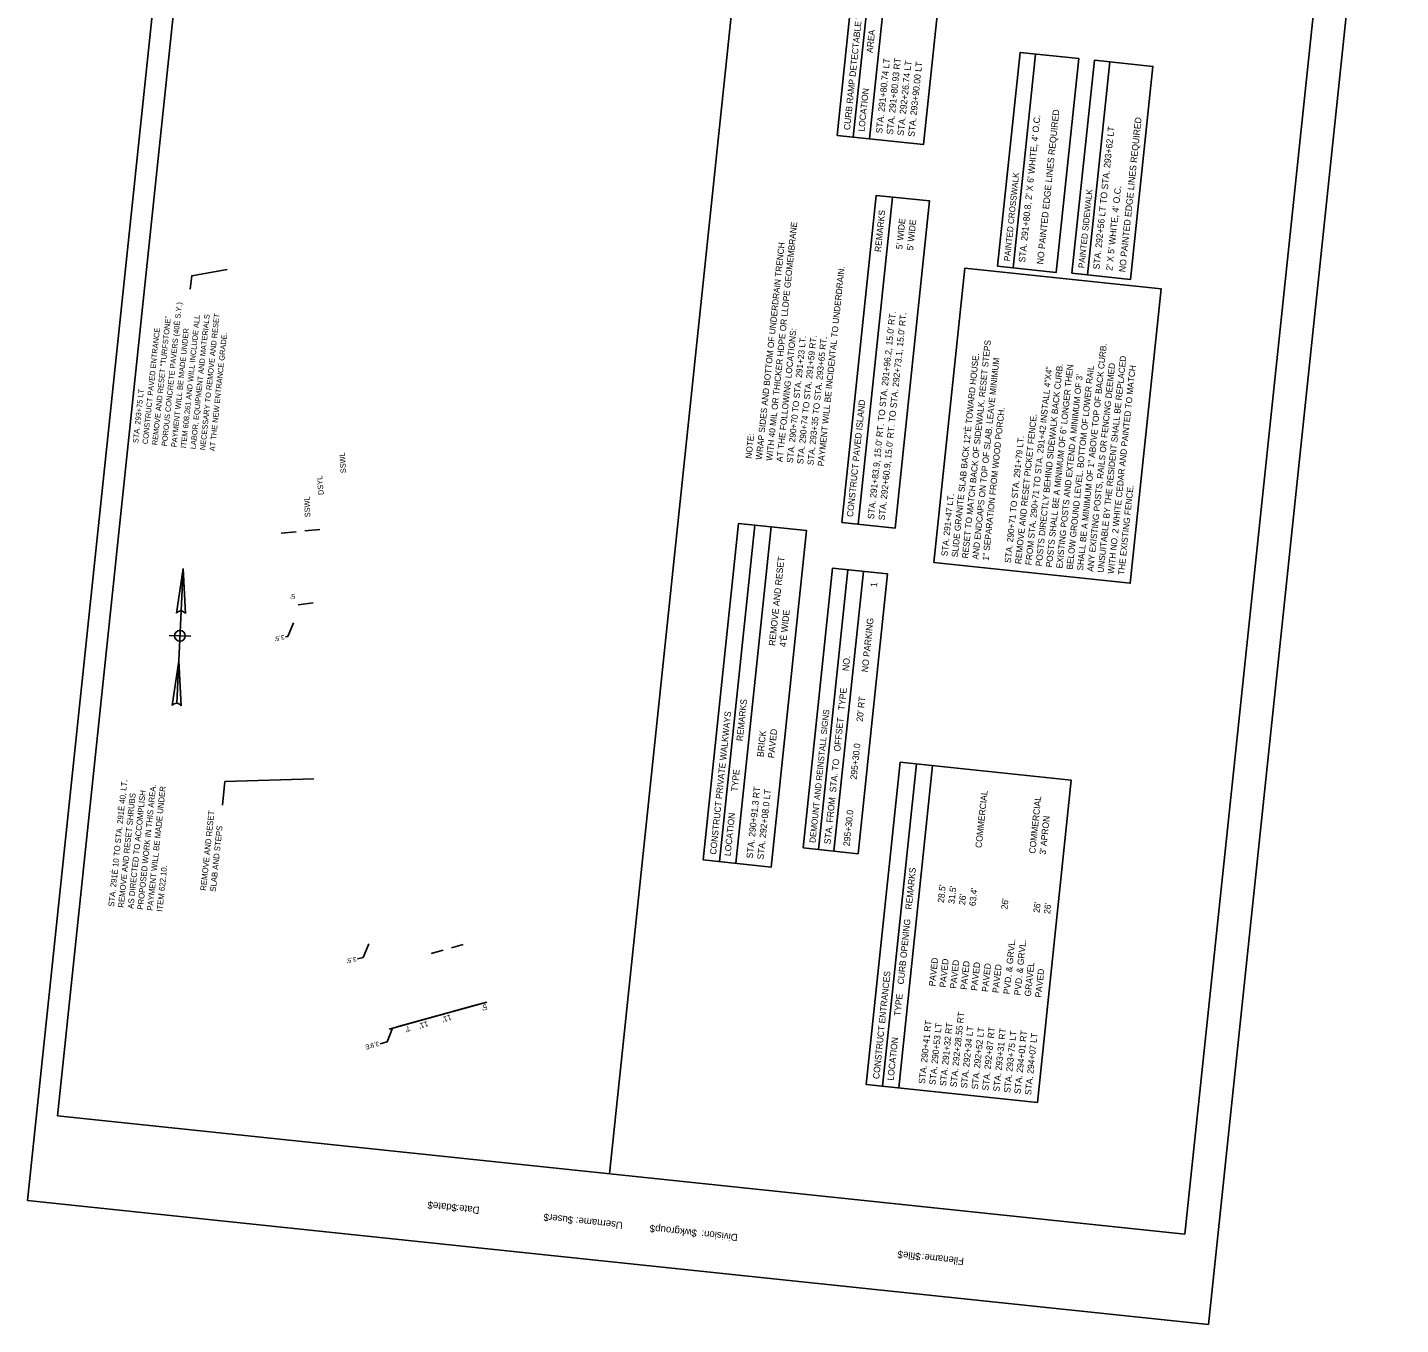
# Model space of a CAD drawing. Extents: x 1111051 to 1111686, y 618367 to 619270.
# Drawn here: x 1111051 to 1111686, y 618367 to 618968 of the extents above; entities that cross this region are included whole.
import ezdxf

# ---------------------------------------------------------------- set-up
doc = ezdxf.new("R2010")
doc.units = 0
for name, color, linetype in [('D_Roadway_Centerline_Text', 7, 'Continuous'), ('MINOR', 7, 'Continuous'), ('S_Roadway_Sidewalks_Paved', 7, 'Continuous'), ('S_Utilities_GuyWire3', 7, 'Continuous')]:
    doc.layers.add(name, color=color, linetype=linetype)

msp = doc.modelspace()

# ---------------------------------------------------------------- linework, layer by layer
at = {"layer": 'D_Roadway_Centerline_Text'}
for p, q in [((1111119.63, 618696.79), (1111122.67, 618717.51)), ((1111122.67, 618717.51), (1111119.81, 618655.07)), ((1111122.67, 618717.51), (1111123.79, 618696.6)), ((1111116.24, 618686.52), (1111126.23, 618686.06)), ((1111117.68, 618654.05), (1111120.71, 618674.77)), ((1111120.71, 618674.77), (1111121.84, 618653.86))]:
    msp.add_line(p, q, dxfattribs=at)
msp.add_circle((1111121.24, 618686.29), 2.5, dxfattribs=at)
for centre in [(1111121.65, 618695.31), (1111119.69, 618652.57)]:
    msp.add_arc(centre, 2.5, 30.93571, 143.82109, dxfattribs=at)
at = {"layer": 'MINOR'}
for p, q in [((1111148.14, 619259.69), (1111064.52, 618464.07)), ((1111586.64, 618409.2), (1111670.26, 619204.81)), ((1111320.11, 618437.21), (1111398.5, 619183.1)), ((1111064.52, 618464.07), (1111586.64, 618409.2))]:
    msp.add_line(p, q, dxfattribs=at)
at = {"layer": 'S_Roadway_Sidewalks_Paved'}
msp.add_lwpolyline([(1111597.62, 618367.35), (1111686.47, 619212.69), (1111139.49, 619270.18), (1111050.64, 618424.84)], close=True, dxfattribs=at)
at = {"layer": 'S_Utilities_GuyWire3'}
for p, q in [((1111433.07, 618917.25), (1111444.25, 619023.7)), ((1111440.6, 618916.46), (1111451.79, 619022.91)), ((1111507.04, 618856.69), (1111517.45, 618955.71)), ((1111541.48, 618853.48), (1111551.85, 618952.09)), ((1111435.31, 618738), (1111451.23, 618889.46)), ((1111371.08, 618581.73), (1111387.46, 618737.58)), ((1111168.1, 618733.85), (1111175.07, 618734.51)), ((1111186.02, 618735.56), (1111179.05, 618734.89)), ((1111378.61, 618580.94), (1111394.99, 618736.79)), ((1111416.95, 618587.31), (1111430.57, 618716.87)), ((1111424.11, 618586.56), (1111437.72, 618716.12)), ((1111176.03, 618700.65), (1111182.96, 618701.63)), ((1111182.96, 618701.63), (1111176.03, 618700.65)), ((1111446.57, 618477.79), (1111462.25, 618626.97)), ((1111454.1, 618477), (1111469.78, 618626.18)), ((1111237.53, 618539.14), (1111243.14, 618540.7)), ((1111252.43, 618543.27), (1111246.99, 618541.76)), ((1111247.94, 618512.42), (1111258.54, 618515.36)), ((1111261.43, 618516.16), (1111250.83, 618513.23)), ((1111240.23, 618510.29), (1111229.62, 618507.36)), ((1111229.63, 618507.36), (1111240.23, 618510.29)), ((1111240.23, 618510.29), (1111250.83, 618513.23)), ((1111250.83, 618513.23), (1111240.23, 618510.29)), ((1111221.69, 618505.16), (1111229.62, 618507.36)), ((1111233.5, 618508.43), (1111222.9, 618505.49))]:
    msp.add_line(p, q, dxfattribs=at)
for points in [[(1111425.53, 618918.04), (1111436.72, 619024.49), (1111476.79, 619020.28), (1111465.6, 618913.83)], [(1111499.88, 618857.45), (1111510.29, 618956.46), (1111537.44, 618953.6), (1111527.03, 618854.59)], [(1111534.32, 618854.23), (1111544.69, 618952.84), (1111571.84, 618949.99), (1111561.47, 618851.37)], [(1111427.78, 618738.79), (1111443.7, 618890.25), (1111468.37, 618887.66), (1111452.45, 618736.2)], [(1111470.37, 618720.19), (1111484.7, 618856.49), (1111575.63, 618846.94), (1111561.31, 618710.63)], [(1111363.54, 618582.52), (1111379.92, 618738.37), (1111411.42, 618735.06), (1111395.04, 618579.21)], [(1111409.79, 618588.06), (1111423.41, 618717.62), (1111448.91, 618714.94), (1111435.29, 618585.38)], [(1111439.03, 618478.58), (1111454.71, 618627.77), (1111533.97, 618619.44), (1111518.29, 618470.25)]]:
    msp.add_lwpolyline(points, close=True, dxfattribs=at)
for points in [[(1111126.02, 618846.76), (1111126.68, 618853.05), (1111143.13, 618855.91)], [(1111170.12, 618685.75), (1111171.14, 618686), (1111173.86, 618692.24)], [(1111140.92, 618607.87), (1111142.07, 618618.81), (1111183.32, 618620.1)], [(1111203.43, 618536.69), (1111206.03, 618537.35), (1111208.76, 618543.59)], [(1111218.06, 618504.15), (1111263.35, 618516.69)], [(1111213.9, 618497.31), (1111217.18, 618498.27), (1111219.68, 618504.6)]]:
    msp.add_lwpolyline(points, dxfattribs=at)

# ---------------------------------------------------------------- texts
at = {"layer": 'MINOR'}
for s, p in [('$date$', (1111249.7, 618422.92)), ('Date:', (1111260.09, 618421.82)), ('$user$', (1111303.48, 618417.26)), ('Username:', (1111326.47, 618414.85)), ('$wkgroup$', (1111360.77, 618411.24)), ('Division:', (1111379.68, 618409.25)), ('$file$', (1111464.42, 618400.35)), ('Filename:', (1111484.44, 618398.24))]:
    msp.add_text(s, height=3.348, rotation=174, dxfattribs=at).set_placement(p)
at = {"layer": 'S_Utilities_GuyWire3'}
for s, height, rotation, p in [('CURB RAMP DETECTABLE WARNING FIELD', 2.9531, 84, (1111431.53, 618920.38)), ('LOCATION               AREA', 2.9531, 84, (1111438.22, 618919.67)), ('STA. 291+80.74 LT', 3.0059, 84, (1111446.43, 618918.81)), ('STA. 291+80.93 RT', 3.0059, 84, (1111451.41, 618918.29)), ('STA. 292+26.74 LT', 3.0059, 84, (1111456.39, 618917.76)), ('STA. 293+90.00 LT', 3.0059, 84, (1111461.37, 618917.24)), ('NO PAINTED EDGE LINES REQUIRED', 3.0059, 83.99894, (1111520.98, 618858.17)), ("STA. 291+80.8, 2' X 6' WHITE, 4' O.C.", 3.0059, 83.99894, (1111512.58, 618859.06)), ('STA. 292+56 LT TO STA. 293+62 LT', 3.0059, 83.99894, (1111547.03, 618855.84)), ('NO PAINTED EDGE LINES REQUIRED', 3.0059, 83.99894, (1111559.02, 618854.58)), ('PAINTED CROSSWALK', 2.8055, 83.99894, (1111505.58, 618859.66)), ('PAINTED SIDEWALK', 2.8055, 83.99894, (1111540.02, 618856.45)), ("2' X 5' WHITE, 4' O.C.", 3.0059, 83.99894, (1111553.02, 618855.21)), ('WITH 40 MIL OR THICKER HDPE OR LLDPE GEOMEMBRANE', 2.88, 84, (1111395.51, 618767.2)), ('REMARKS', 2.953, 84, (1111445.83, 618863.9)), ("5' WIDE", 2.953, 84, (1111455.74, 618865.16)), ("5' WIDE", 2.953, 84, (1111460.72, 618864.64)), ('WRAP SIDES AND BOTTOM OF UNDERDRAIN TRENCH', 2.88, 84, (1111390.74, 618767.71)), ('PAYMENT WILL BE INCIDENTAL TO UNDERDRAIN.', 2.88, 84, (1111419.38, 618764.7)), ('POROUS CONCRETE PAVERS (40È S.Y.)', 2.497, 84, (1111115.21, 618774.01)), ('ITEM 608.261 AND WILL INCLUDE ALL', 2.497, 84, (1111124.07, 618773.08)), ('LABOR, EQUIPMENT AND MATERIALS', 2.497, 84, (1111128.5, 618772.61)), ('NECESSARY TO REMOVE AND RESET', 2.497, 84, (1111132.93, 618772.15)), ("STA. 291+83.9, 15.0' RT. TO STA. 291+96.2, 15.0' RT.", 2.9531, 84, (1111442.61, 618740.2)), ("STA. 292+60.9, 15.0' RT. TO STA. 292+73.1, 15.0' RT.", 2.9531, 84, (1111447.59, 618739.67)), ('CONSTRUCT PAVED ENTRANCE', 2.497, 84, (1111106.34, 618774.94)), ('REMOVE AND RESET "TURFSTONE"', 2.497, 84, (1111110.77, 618774.47)), ('PAYMENT WILL BE MADE UNDER', 2.497, 84, (1111119.64, 618773.54)), ('AT THE FOLLOWING LOCATIONS:', 2.88, 84, (1111400.28, 618766.7)), ('AT THE NEW ENTRANCE GRADE.', 2.497, 84, (1111137.36, 618771.68)), ('STA. 290+70 TO STA. 291+23 LT.', 2.88, 84, (1111405.06, 618766.2)), ('STA. 290+74 TO STA. 291+59 RT.', 2.88, 84, (1111409.83, 618765.7)), ('STA. 293+35 TO STA. 293+65 RT.', 2.88, 84, (1111414.61, 618765.2)), ('RESET TO MATCH BACK OF SIDEWALK. RESET STEPS', 2.88, 84, (1111486.18, 618722.02)), ('SHALL BE A MINIMUM OF 1" ABOVE TOP OF BACK CURB.', 2.88, 84, (1111539.41, 618716.38)), ('SLIDE GRANITE SLAB BACK 12"È TOWARD HOUSE.', 2.88, 84, (1111481.4, 618722.52)), ('AND ENDCAPS ON TOP OF SLAB. LEAVE MINIMUM', 2.88, 84, (1111490.95, 618721.52)), ('UNSUITABLE BY THE RESIDENT SHALL BE REPLACED', 2.88, 84, (1111548.95, 618715.38)), ('FROM STA. 290+71 TO STA. 291+42 INSTALL 4"X4"', 2.88, 84, (1111515.54, 618718.89)), ('POSTS DIRECTLY BEHIND SIDEWALK BACK CURB.', 2.88, 84, (1111520.31, 618718.39)), ('POSTS SHALL BE A MINIMUM OF 6" LONGER THEN', 2.88, 84, (1111525.08, 618717.89)), ("EXISTING POSTS AND EXTEND A MINIMUM OF 3'", 2.88, 84, (1111529.86, 618717.38)), ('BELOW GROUND LEVEL. BOTTOM OF LOWER RAIL', 2.88, 84, (1111534.63, 618716.88)), ('ANY EXISTING POSTS, RAILS OR FENCING DEEMED', 2.88, 84, (1111544.18, 618715.88)), ('WITH NO. 2 WHITE CEDAR AND PAINTED TO MATCH', 2.88, 84, (1111553.73, 618714.88)), ('STA. 293+75 LT', 2.497, 84, (1111101.91, 618775.41)), ('CONSTRUCT PAVED ISLAND', 2.9531, 84, (1111432.93, 618741.21)), ('1" SEPARATION FROM WOOD PORCH.', 2.88, 84, (1111495.72, 618721.02)), ('REMOVE AND RESET PICKET FENCE.', 2.88, 84, (1111510.76, 618719.39)), ('NOTE:', 2.88, 84, (1111385.96, 618768.21)), ('STA. 290+71 TO STA. 291+79 LT.', 2.88, 84, (1111505.99, 618719.89)), ('SSWL', 2.55, 93.89742, (1111198.23, 618761.71)), ('DSYL', 2.55, 95.07693, (1111187.87, 618751.64)), ('SSWL', 2.55, 92.37304, (1111181.64, 618741.25)), ('STA. 291+47 LT.', 2.88, 84, (1111476.63, 618723.02)), ('THE EXISTING FENCE.', 2.88, 84, (1111558.5, 618714.37)), ('REMOVE AND RESET', 3.0059, 84, (1111396.86, 618681.52)), ("5'", 2.168, 184.89461, (1111174.44, 618705.72)), ('1', 3.01, 84, (1111443.98, 618708.73)), ("4'È WIDE", 3.006, 84, (1111401.84, 618681)), ('NO PARKING', 3.006, 84, (1111439.84, 618669.32)), ("3.5'", 2.168, 192.72457, (1111169.39, 618686.79)), ('STA. FROM  STA. TO   OFFSET   TYPE       NO.', 3.0059, 84, (1111422.49, 618589.67)), ('LOCATION         TYPE            REMARKS', 2.9531, 84, (1111376.23, 618584.15)), ("20' RT", 3.006, 84, (1111437.42, 618646.36)), ('CONSTRUCT PRIVATE WALKWAYS', 2.9531, 84, (1111369.54, 618584.86)), ('DEMOUNT AND REINSTALL SIGNS', 2.8055, 84, (1111415.49, 618590.28)), ('BRICK', 3.006, 84, (1111391.45, 618630.04)), ('PAVED', 3.006, 84, (1111396.43, 618629.51)), ('295+30.0', 3.006, 84, (1111434.61, 618619.56)), ('STA. 291È 10 TO STA. 291È 40, LT.', 2.7, 84, (1111090.73, 618560.74)), ('PROPOSED WORK IN THIS AREA.', 2.7, 84, (1111104.15, 618559.33)), ('REMOVE AND RESET SHRUBS', 2.7, 84, (1111095.2, 618560.27)), ('AS DIRECTED TO ACCOMPLISH', 2.7, 84, (1111099.68, 618559.8)), ('PAYMENT WILL BE MADE UNDER', 2.7, 84, (1111108.63, 618558.86)), ('STA. 290+91.3 RT', 3.0059, 84, (1111386.51, 618583.07)), ('STA. 292+08.0 LT', 3.0059, 84, (1111391.49, 618582.55)), ('COMMERCIAL', 2.953, 84, (1111492.48, 618587.93)), ('COMMERCIAL', 2.953, 84, (1111517.33, 618585.32)), ('REMOVE AND RESET', 2.7, 84, (1111133.32, 618568.13)), ('295+30.0', 3.006, 84, (1111431.37, 618588.74)), ('SLAB AND STEPS', 2.7, 84, (1111137.8, 618567.66)), ("3' APRON", 2.953, 84, (1111522.15, 618584.81)), ('ITEM 622.10.', 2.7, 84, (1111113.11, 618558.39)), ('LOCATION         TYPE    CURB OPENING    REMARKS', 2.9531, 84, (1111451.72, 618480.21)), ("28.5'", 2.953, 84, (1111475.02, 618562.53)), ("31.5'", 2.953, 84, (1111479.92, 618562.02)), ("26'", 2.953, 84, (1111484.81, 618561.5)), ("63.4'", 2.953, 84, (1111489.65, 618560.99)), ("26'", 2.953, 84, (1111504.42, 618559.44)), ("26'", 2.953, 84, (1111519.32, 618557.88)), ("26'", 2.953, 84, (1111524.21, 618557.36)), ('PVD. & GRVL.', 2.9531, 84, (1111505.46, 618520.2)), ('PVD. & GRVL.', 2.9531, 84, (1111510.43, 618519.68)), ("3.5'", 2.168, 192.72457, (1111202.74, 618537.69)), ('PAVED', 2.953, 84, (1111470.95, 618523.83)), ('PAVED', 2.953, 84, (1111475.85, 618523.31)), ('PAVED', 2.953, 84, (1111480.74, 618522.8)), ('PAVED', 2.953, 84, (1111485.58, 618522.29)), ('PAVED', 2.953, 84, (1111490.45, 618521.78)), ('PAVED', 2.953, 84, (1111495.46, 618521.25)), ('PAVED', 2.953, 84, (1111500.36, 618520.74)), ('GRAVEL', 2.953, 84, (1111515.25, 618519.17)), ('CONSTRUCT ENTRANCES', 2.9531, 84, (1111445.04, 618480.92)), ('PAVED', 2.953, 84, (1111520.14, 618518.66)), ("5'", 2.55, 199.66361, (1111263.02, 618515.85)), ("11'", 2.55, 198.66415, (1111246.53, 618510.96)), ('STA. 292+28.55 RT', 2.9531, 84, (1111480.84, 618477.15)), ("7'", 2.55, 204.18962, (1111227.31, 618505.95)), ("11'", 2.55, 198.66415, (1111235.74, 618507.98)), ('STA. 290+41 RT', 2.9531, 84, (1111466.21, 618478.69)), ('STA. 290+53 LT', 2.9531, 84, (1111471.1, 618478.18)), ('STA. 291+32 RT', 2.9531, 84, (1111476, 618477.66)), ('STA. 292+34 LT', 2.9531, 84, (1111485.71, 618476.64)), ('STA. 292+52 LT', 2.9531, 84, (1111490.72, 618476.11)), ('STA. 292+87 RT', 2.9531, 84, (1111495.61, 618475.6)), ('STA. 293+31 RT', 2.9531, 84, (1111500.72, 618475.06)), ('STA. 293+75 LT', 2.9531, 84, (1111505.69, 618474.54)), ('STA. 294+01 RT', 2.9531, 84, (1111510.5, 618474.03)), ('STA. 294+07 LT', 2.9531, 84, (1111515.4, 618473.52)), ("3.9'È", 2.168, 194.80486, (1111213.26, 618498.49))]:
    msp.add_text(s, height=height, rotation=rotation, dxfattribs=at).set_placement(p)

doc.saveas('drawing.dxf')
